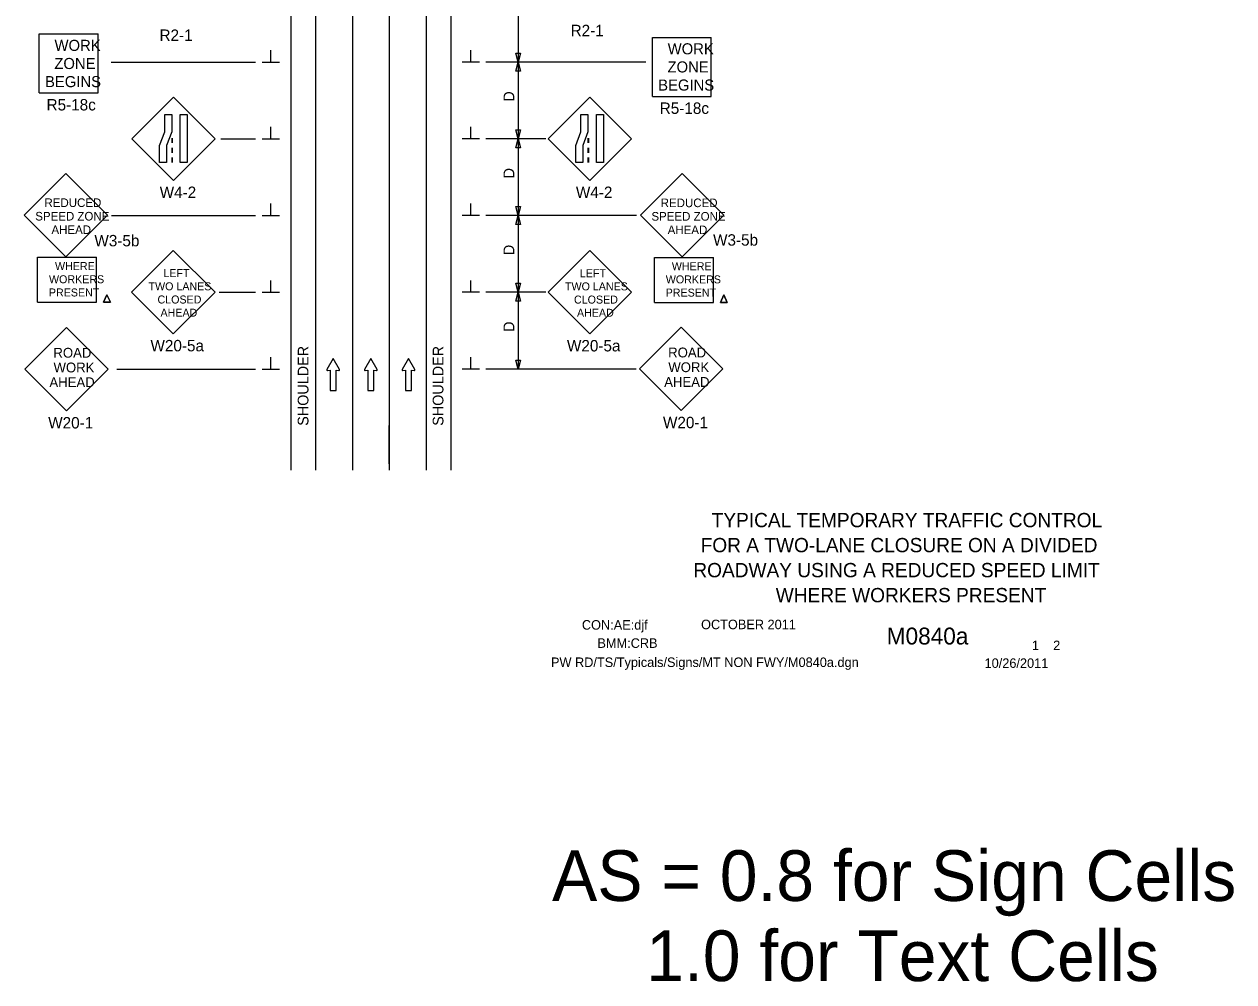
# Model space of a CAD drawing. Extents: x 16726 to 18475, y 5729 to 6921.
# Drawn here: x 16727 to 17515, y 5729 to 6353 of the extents above; entities that cross this region are included whole.
import ezdxf

# ---------------------------------------------------------------- set-up
doc = ezdxf.new("R2010")
doc.units = 0
for name, color, linetype in [('ALI_LEGAL_EX', 7, 'Continuous'), ('BORDER', 7, 'Continuous'), ('BORDER_SIGNAL_WO', 7, 'Continuous'), ('MT_SCRATCH_LEVEL_E', 7, 'Continuous'), ('PAVT_EDGE_EX', 7, 'Continuous'), ('TRAFFIC_SIGNS_PR', 7, 'Continuous'), ('TYPICAL_TEXT_DIMEN_PR', 7, 'Continuous')]:
    doc.layers.add(name, color=color, linetype=linetype)

msp = doc.modelspace()

# ---------------------------------------------------------------- linework, layer by layer
at = {"layer": 'ALI_LEGAL_EX'}
for p, q in [((16941.23, 6891.16), (16941.23, 6061.98)), ((16965.23, 6891.16), (16965.23, 6061.98)), ((16965.23, 6891.16), (16965.23, 6061.98))]:
    msp.add_line(p, q, dxfattribs=at)
for points in [[(16941.23, 6291.16), (16941.23, 6266.16)], [(16965.23, 6291.16), (16965.23, 6266.16)], [(16941.23, 6191.16), (16941.23, 6166.16)], [(16965.23, 6191.16), (16965.23, 6166.16)], [(16941.23, 6091.16), (16941.23, 6066.16)], [(16965.23, 6066.16), (16965.23, 6091.16)], [(16965.23, 6091.16), (16965.23, 6066.16)]]:
    msp.add_lwpolyline(points, dxfattribs=at)
at = {"layer": 'MT_SCRATCH_LEVEL_E'}
for p, q in [((16928.67, 6134.8), (16924.56, 6127.56)), ((16928.67, 6134.8), (16924.56, 6127.56)), ((16932.82, 6127.56), (16928.67, 6134.8)), ((16932.82, 6127.56), (16928.67, 6134.8)), ((16953.2, 6134.8), (16949.09, 6127.56)), ((16953.2, 6134.8), (16949.09, 6127.56)), ((16957.35, 6127.56), (16953.2, 6134.8)), ((16957.35, 6127.56), (16953.2, 6134.8)), ((16977.76, 6134.8), (16973.65, 6127.56)), ((16977.76, 6134.8), (16973.65, 6127.56)), ((16981.9, 6127.56), (16977.76, 6134.8)), ((16981.9, 6127.56), (16977.76, 6134.8)), ((16925.04, 6126.88), (16926.82, 6127.19)), ((16925.04, 6126.88), (16926.82, 6127.19)), ((16926.82, 6127.19), (16926.82, 6113.93)), ((16926.82, 6127.19), (16926.82, 6113.93)), ((16930.56, 6113.93), (16930.56, 6127.19)), ((16930.56, 6127.19), (16932.34, 6126.88)), ((16930.56, 6113.93), (16930.56, 6127.19)), ((16930.56, 6127.19), (16932.34, 6126.88)), ((16949.57, 6126.88), (16951.35, 6127.19)), ((16949.57, 6126.88), (16951.35, 6127.19)), ((16951.35, 6127.19), (16951.35, 6113.93)), ((16951.35, 6127.19), (16951.35, 6113.93)), ((16955.09, 6113.93), (16955.09, 6127.19)), ((16955.09, 6127.19), (16956.87, 6126.88)), ((16955.09, 6113.93), (16955.09, 6127.19)), ((16955.09, 6127.19), (16956.87, 6126.88)), ((16974.13, 6126.88), (16975.9, 6127.19)), ((16974.13, 6126.88), (16975.9, 6127.19)), ((16975.9, 6127.19), (16975.9, 6113.93)), ((16975.9, 6127.19), (16975.9, 6113.93)), ((16979.65, 6113.93), (16979.65, 6127.19)), ((16979.65, 6127.19), (16981.42, 6126.88)), ((16979.65, 6113.93), (16979.65, 6127.19)), ((16979.65, 6127.19), (16981.42, 6126.88)), ((16926.82, 6113.93), (16930.56, 6113.93)), ((16926.82, 6113.93), (16930.56, 6113.93)), ((16951.35, 6113.93), (16955.09, 6113.93)), ((16951.35, 6113.93), (16955.09, 6113.93)), ((16975.9, 6113.93), (16979.65, 6113.93)), ((16975.9, 6113.93), (16979.65, 6113.93))]:
    msp.add_line(p, q, dxfattribs=at)
for centre, start, end in [((16924.97, 6127.33), 150.42484, 279.96381), ((16924.97, 6127.33), 150.42484, 279.96381), ((16932.41, 6127.34), 260.03619, 29.77312), ((16932.41, 6127.34), 260.03619, 29.77312), ((16949.49, 6127.33), 150.42484, 279.96381), ((16949.49, 6127.33), 150.42484, 279.96381), ((16956.94, 6127.34), 260.03619, 29.77312), ((16956.94, 6127.34), 260.03619, 29.77312), ((16974.05, 6127.33), 150.42484, 279.96381), ((16974.05, 6127.33), 150.42484, 279.96381), ((16981.49, 6127.34), 260.03619, 29.77312), ((16981.49, 6127.34), 260.03619, 29.77312)]:
    msp.add_arc(centre, 0.463, start, end, dxfattribs=at)
at = {"layer": 'PAVT_EDGE_EX'}
for p, q in [((16901.23, 6916.78), (16901.23, 6061.98)), ((16917.23, 6916.78), (16917.23, 6061.98)), ((16989.23, 6916.78), (16989.23, 6061.98)), ((17005.23, 6916.78), (17005.23, 6061.98)), ((16917.23, 6891.16), (16917.23, 6061.98))]:
    msp.add_line(p, q, dxfattribs=at)
at = {"layer": 'TRAFFIC_SIGNS_PR'}
for p, q in [((16737.25, 6307.82), (16737.25, 6346.22)), ((16737.25, 6346.22), (16775.65, 6346.22)), ((16775.65, 6307.82), (16775.65, 6346.22)), ((17136.56, 6305.58), (17136.56, 6343.98)), ((17136.56, 6343.98), (17174.96, 6343.98)), ((17174.96, 6305.58), (17174.96, 6343.98)), ((16737.25, 6307.82), (16775.65, 6307.82)), ((16824.78, 6305.09), (16797.62, 6277.93)), ((16851.93, 6277.93), (16824.78, 6305.09)), ((17095.82, 6305.09), (17068.67, 6277.93)), ((17122.98, 6277.93), (17095.82, 6305.09)), ((17136.56, 6305.58), (17174.96, 6305.58)), ((16823.53, 6278.43), (16823.53, 6275.23)), ((16823.93, 6278.43), (16823.93, 6275.23)), ((17094.58, 6278.43), (17094.58, 6275.23)), ((17094.98, 6278.43), (17094.98, 6275.23)), ((16797.62, 6277.93), (16824.78, 6250.78)), ((16823.53, 6272.03), (16823.53, 6268.83)), ((16823.93, 6272.03), (16823.93, 6268.83)), ((16824.78, 6250.78), (16851.93, 6277.93)), ((17068.67, 6277.93), (17095.82, 6250.78)), ((17094.58, 6272.03), (17094.58, 6268.83)), ((17094.98, 6272.03), (17094.98, 6268.83)), ((17095.82, 6250.78), (17122.98, 6277.93)), ((16823.53, 6265.63), (16823.53, 6262.43)), ((16823.93, 6265.63), (16823.93, 6262.43)), ((17094.58, 6265.63), (17094.58, 6262.43)), ((17094.98, 6265.63), (17094.98, 6262.43)), ((16754.64, 6255.32), (16727.49, 6228.17)), ((16781.8, 6228.17), (16754.64, 6255.32)), ((17155.93, 6255.22), (17128.78, 6228.07)), ((17183.08, 6228.07), (17155.93, 6255.22)), ((16727.49, 6228.17), (16754.64, 6201.01)), ((16754.64, 6201.01), (16781.8, 6228.17)), ((17128.78, 6228.07), (17155.93, 6200.92)), ((17155.93, 6200.92), (17183.08, 6228.07)), ((16736.25, 6200.7), (16774.65, 6200.7)), ((16736.25, 6171.38), (16736.25, 6200.7)), ((16774.65, 6171.38), (16774.65, 6200.7)), ((16824.6, 6205.15), (16797.45, 6178)), ((16851.75, 6178), (16824.6, 6205.15)), ((17095.82, 6205.1), (17068.67, 6177.95)), ((17122.98, 6177.95), (17095.82, 6205.1)), ((17137.94, 6200.6), (17176.34, 6200.6)), ((17137.94, 6171.29), (17137.94, 6200.6)), ((17176.34, 6171.29), (17176.34, 6200.6)), ((16797.45, 6178), (16824.6, 6150.85)), ((16824.6, 6150.85), (16851.75, 6178)), ((17068.67, 6177.95), (17095.82, 6150.8)), ((17095.82, 6150.8), (17122.98, 6177.95)), ((16736.25, 6171.38), (16774.65, 6171.38)), ((17137.94, 6171.29), (17176.34, 6171.29)), ((16754.96, 6154.9), (16727.81, 6127.75)), ((16782.12, 6127.75), (16754.96, 6154.9)), ((17155.32, 6155.07), (17128.17, 6127.92)), ((17182.47, 6127.92), (17155.32, 6155.07)), ((16727.81, 6127.75), (16754.96, 6100.59)), ((16754.96, 6100.59), (16782.12, 6127.75)), ((17128.17, 6127.92), (17155.32, 6100.77)), ((17155.32, 6100.77), (17182.47, 6127.92))]:
    msp.add_line(p, q, dxfattribs=at)
for points in [[(16823.53, 6293.67), (16823.53, 6282.49), (16820.19, 6273.61), (16820.19, 6262.43), (16815.69, 6262.43), (16815.69, 6273.61), (16819.04, 6282.49), (16819.04, 6293.67)], [(16833.67, 6293.67), (16833.67, 6262.43), (16829.17, 6262.43), (16829.17, 6293.67)], [(17094.58, 6293.67), (17094.58, 6282.49), (17091.23, 6273.61), (17091.23, 6262.43), (17086.74, 6262.43), (17086.74, 6273.61), (17090.08, 6282.49), (17090.08, 6293.67)], [(17104.71, 6293.67), (17104.71, 6262.43), (17100.22, 6262.43), (17100.22, 6293.67)]]:
    msp.add_lwpolyline(points, close=True, dxfattribs=at)
for points in [[(16781.4, 6176.32), (16779.16, 6171.38)], [(16779.16, 6171.38), (16781.4, 6176.32)], [(16783.64, 6171.38), (16781.4, 6176.32)], [(16781.4, 6176.32), (16783.64, 6171.38)], [(17183.09, 6176.22), (17180.85, 6171.29)], [(17180.85, 6171.29), (17183.09, 6176.22)], [(17185.32, 6171.29), (17183.09, 6176.22)], [(17183.09, 6176.22), (17185.32, 6171.29)], [(16779.16, 6171.38), (16783.64, 6171.38)], [(16783.64, 6171.38), (16779.16, 6171.38)], [(17180.85, 6171.29), (17185.32, 6171.29)], [(17185.32, 6171.29), (17180.85, 6171.29)]]:
    msp.add_lwpolyline(points, dxfattribs=at)
at = {"layer": 'TYPICAL_TEXT_DIMEN_PR'}
for p, q in [((17049.23, 6377.89), (17049.23, 6327.89)), ((16888.1, 6327.89), (16888.1, 6335.67)), ((17018.35, 6327.89), (17018.35, 6335.67)), ((17049.23, 6327.89), (17047.66, 6333.75)), ((17047.66, 6333.75), (17049.23, 6333.75)), ((17049.23, 6333.75), (17050.8, 6333.75)), ((17050.8, 6333.75), (17049.23, 6327.89)), ((16784.09, 6327.89), (16878.23, 6327.89)), ((16882.48, 6327.89), (16893.73, 6327.89)), ((17023.98, 6327.89), (17012.73, 6327.89)), ((17132.34, 6327.89), (17028.23, 6327.89)), ((17047.66, 6322.03), (17049.23, 6327.89)), ((17049.23, 6327.89), (17050.8, 6322.03)), ((17049.23, 6327.89), (17049.23, 6277.89)), ((17049.23, 6322.03), (17047.66, 6322.03)), ((17050.8, 6322.03), (17049.23, 6322.03)), ((16888.1, 6277.89), (16888.1, 6285.67)), ((17018.35, 6277.89), (17018.35, 6285.67)), ((17049.23, 6277.89), (17047.66, 6283.75)), ((17047.66, 6283.75), (17049.23, 6283.75)), ((17049.23, 6283.75), (17050.8, 6283.75)), ((17050.8, 6283.75), (17049.23, 6277.89)), ((16855.45, 6277.89), (16878.23, 6277.89)), ((16882.48, 6277.89), (16893.73, 6277.89)), ((17023.98, 6277.89), (17012.73, 6277.89)), ((17067.23, 6277.89), (17028.23, 6277.89)), ((17047.66, 6272.03), (17049.23, 6277.89)), ((17049.23, 6272.03), (17047.66, 6272.03)), ((17049.23, 6277.89), (17049.23, 6227.89)), ((17049.23, 6277.89), (17050.8, 6272.03)), ((17050.8, 6272.03), (17049.23, 6272.03)), ((16888.1, 6227.89), (16888.1, 6235.67)), ((17018.35, 6227.89), (17018.35, 6235.67)), ((17049.23, 6227.89), (17047.66, 6233.75)), ((17047.66, 6233.75), (17049.23, 6233.75)), ((17049.23, 6233.75), (17050.8, 6233.75)), ((17050.8, 6233.75), (17049.23, 6227.89)), ((16784.34, 6227.89), (16878.23, 6227.89)), ((16882.48, 6227.89), (16893.73, 6227.89)), ((17023.98, 6227.89), (17012.73, 6227.89)), ((17126.25, 6227.89), (17028.23, 6227.89)), ((17047.66, 6222.03), (17049.23, 6227.89)), ((17049.23, 6227.89), (17049.23, 6177.89)), ((17049.23, 6227.89), (17050.8, 6222.03)), ((17049.23, 6222.03), (17047.66, 6222.03)), ((17050.8, 6222.03), (17049.23, 6222.03)), ((16888.1, 6177.89), (16888.1, 6185.67)), ((17018.35, 6177.89), (17018.35, 6185.67)), ((16854.48, 6177.89), (16878.23, 6177.89)), ((16882.48, 6177.89), (16893.73, 6177.89)), ((17023.98, 6177.89), (17012.73, 6177.89)), ((17067.23, 6177.89), (17028.23, 6177.89)), ((17049.23, 6177.89), (17047.66, 6183.75)), ((17047.66, 6183.75), (17049.23, 6183.75)), ((17047.66, 6172.03), (17049.23, 6177.89)), ((17049.23, 6183.75), (17050.8, 6183.75)), ((17050.8, 6183.75), (17049.23, 6177.89)), ((17049.23, 6177.89), (17049.23, 6127.89)), ((17049.23, 6177.89), (17050.8, 6172.03)), ((17049.23, 6172.03), (17047.66, 6172.03)), ((17050.8, 6172.03), (17049.23, 6172.03)), ((16888.1, 6127.89), (16888.1, 6135.67)), ((17018.35, 6127.89), (17018.35, 6135.67)), ((17049.23, 6127.89), (17047.66, 6133.75)), ((17047.66, 6133.75), (17049.23, 6133.75)), ((17049.23, 6133.75), (17050.8, 6133.75)), ((17050.8, 6133.75), (17049.23, 6127.89)), ((16787.76, 6127.89), (16878.23, 6127.89)), ((16882.48, 6127.89), (16893.73, 6127.89)), ((17023.98, 6127.89), (17012.73, 6127.89)), ((17126.04, 6127.89), (17028.23, 6127.89))]:
    msp.add_line(p, q, dxfattribs=at)

# ---------------------------------------------------------------- texts
at = {"layer": 'BORDER'}
for s, p in [('TYPICAL TEMPORARY TRAFFIC CONTROL', (17175.21, 6024.8)), ('FOR A TWO-LANE CLOSURE ON A DIVIDED', (17168.02, 6008.5)), ('ROADWAY USING A REDUCED SPEED LIMIT ', (17163.25, 5992.2)), ('WHERE WORKERS PRESENT', (17216.92, 5975.9))]:
    msp.add_text(s, height=9.3, dxfattribs=at).set_placement(p)
at = {"layer": 'BORDER_SIGNAL_WO'}
for s, height, p in [('CON:AE:djf', 6.2, (17090.69, 5958.06)), ('    OCTOBER 2011    ', 6.2, (17159.08, 5958.34)), ('    M0840a   ', 11, (17272.86, 5948.38)), ('BMM:CRB   ', 6.2, (17100.81, 5946.17)), (' 1    2 ', 6.2, (17381.45, 5944.7)), ('PW RD/TS/Typicals/Signs/MT NON FWY/M0840a.dgn    ', 6.2, (17070.55, 5933.71)), ('10/26/2011    ', 6.2, (17352.93, 5933.13)), ('AS = 0.8 for Sign Cells', 33.0301, (17071.24, 5781.25)), ('     1.0 for Text Cells', 33.0301, (17071.24, 5729.02))]:
    msp.add_text(s, height=height, dxfattribs=at).set_placement(p)
at = {"layer": 'TRAFFIC_SIGNS_PR'}
for s, height, p in [('R2-1', 7.44, (16815.61, 6341.71)), ('R2-1', 7.44, (17083.35, 6344.79)), ('WORK', 7.217, (16747.25, 6335.19)), ('WORK', 7.217, (17146.56, 6332.95)), ('ZONE', 7.217, (16747.13, 6323.38)), ('ZONE', 7.217, (17146.45, 6321.14)), ('BEGINS', 7.217, (16741.05, 6311.57)), ('BEGINS', 7.217, (17140.37, 6309.33)), ('R5-18c', 7.44, (16742.06, 6296.38)), ('R5-18c', 7.44, (17141.38, 6294.14)), ('W4-2', 7.44, (16815.74, 6239.34)), ('W4-2', 7.44, (17086.78, 6239.34)), ('REDUCED', 5.6, (16740.7, 6233.47)), ('REDUCED', 5.6, (17141.99, 6233.38)), ('SPEED ZONE', 5.6, (16734.69, 6224.67)), ('SPEED ZONE', 5.6, (17135.98, 6224.58)), ('AHEAD', 5.6, (16745.25, 6215.87)), ('W3-5b', 7.44, (16773.21, 6207.83)), ('AHEAD', 5.6, (17146.54, 6215.78)), ('W3-5b', 7.44, (17176.11, 6208.28)), ('WHERE', 5.2, (16747.56, 6192.38)), ('LEFT', 5.2, (16818.14, 6187.79)), ('LEFT', 5.2, (17089.36, 6187.74)), ('WHERE', 5.2, (17149.25, 6192.29)), ('WORKERS', 5.2, (16743.64, 6183.78)), ('TWO LANES', 5.2, (16808.46, 6179.19)), ('TWO LANES', 5.2, (17079.68, 6179.14)), ('WORKERS', 5.2, (17145.32, 6183.69)), ('PRESENT', 5.2, (16743.57, 6175.18)), ('PRESENT', 5.2, (17145.25, 6175.09)), ('CLOSED', 5.2, (16814.31, 6170.59)), ('CLOSED', 5.2, (17085.53, 6170.54)), ('AHEAD', 5.2, (16816.26, 6161.99)), ('AHEAD', 5.2, (17087.48, 6161.94)), ('W20-5a', 7.44, (16809.74, 6139.41)), ('W20-5a', 7.44, (17080.96, 6139.36)), ('ROAD', 6.4, (16746.51, 6135.28)), ('ROAD', 6.4, (17146.86, 6135.46)), ('WORK', 6.4, (16746.61, 6125.68)), ('WORK', 6.4, (17146.97, 6125.86)), ('AHEAD', 6.4, (16743.92, 6116.08)), ('AHEAD', 6.4, (17144.28, 6116.26)), ('W20-1', 7.44, (16743.13, 6089.15)), ('W20-1', 7.44, (17143.49, 6089.33))]:
    msp.add_text(s, height=height, dxfattribs=at).set_placement(p)
at = {"layer": 'TYPICAL_TEXT_DIMEN_PR'}
for s, p in [('D', (17046.67, 6302.11)), ('D', (17046.67, 6252.11)), ('D', (17046.67, 6202.11)), ('D', (17046.67, 6152.11)), ('SHOULDER', (16912.61, 6090.91)), ('SHOULDER', (17000.51, 6090.91))]:
    msp.add_text(s, height=7, rotation=90, dxfattribs=at).set_placement(p)

doc.saveas('drawing.dxf')
